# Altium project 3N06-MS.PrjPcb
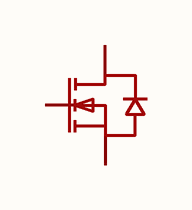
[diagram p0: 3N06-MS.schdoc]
1 sheet, 1 parts. Net scope: global (net labels, ports and power ports of the same name join across sheets).

## Sheet 3N06-MS.schdoc
size 127 x 101 mm

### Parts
U?  3n06-ms  [SOT-89-3_L4.5-W2.4-P1.50-LS4.0-BR]  (value not drawn)

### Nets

Not connected (* = marked no-connect by the designer): U? 1(G) 2(D) 3(S)

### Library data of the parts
U? = 3n06-ms: 类型:1个N沟道;漏源电压(Vdss):60V;连续漏极电流(Id):3A;导通电阻(RDS(on)@Vgs,Id):105mΩ@10V;功率(Pd):350mW;; Manufacturer: MSKSEMI(美森科); AddInBom: yes; ModelId: dde435042bae4b9691e74da94cf9d9f3; ModelTransform: 177.165,161.417,0,90,0,0,-2.323,0,0; Drain Source Voltage (Vdss): 60V; Continuous Drain Current (Id): 3A; Power Dissipation (Pd): 350mW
